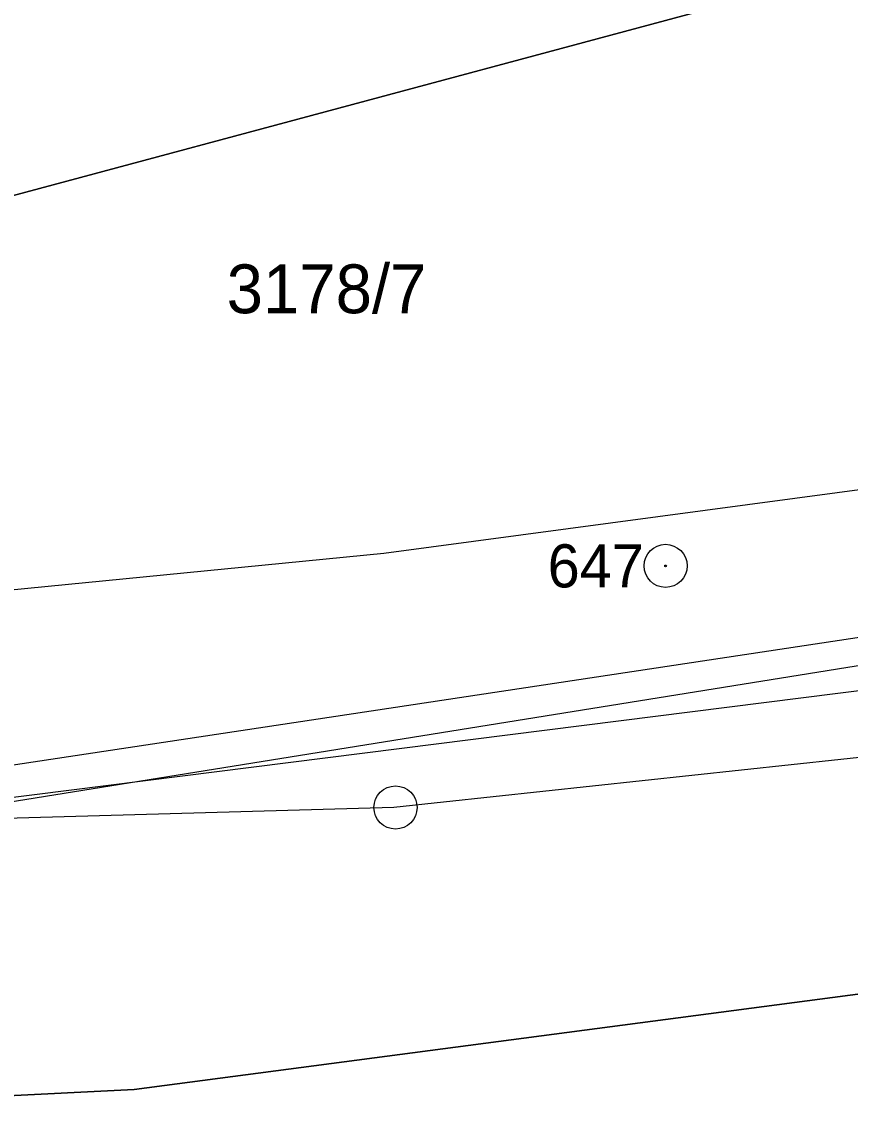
# Model space of a CAD drawing. Extents: x -728802 to -728097, y -1073200 to -1072700.
# Drawn here: x -728474.88 to -728446.06, y -1073055.04 to -1073016.93 of the extents above; entities that cross this region are included whole.
import ezdxf

# ---------------------------------------------------------------- set-up
doc = ezdxf.new("R2010")
doc.units = 0
for name, color, linetype in [('A5_JŽM', 7, 'Continuous'), ('body_ZBP', 7, 'Continuous'), ('Hranice parcel', 7, 'Continuous')]:
    doc.layers.add(name, color=color, linetype=linetype)

msp = doc.modelspace()

# ---------------------------------------------------------------- linework, layer by layer
at = {"layer": 'A5_JŽM'}
for points in [[(-728320.8, -1073026.914), (-728374.008, -1073033.722), (-728429.095, -1073040.747), (-728461.932, -1073044.273), (-728481.199, -1073044.815), (-728499.353, -1073043.648), (-728506.01, -1073042.737), (-728514.574, -1073041.329), (-728535.848, -1073035.998), (-728561.353, -1073026.113), (-728583.963, -1073013.524), (-728603.757, -1072998.891), (-728619.185, -1072984.418), (-728634.193, -1072966.825), (-728646.078, -1072949.194), (-728656.182, -1072930.072), (-728664.987, -1072910.227), (-728668.627, -1072901.808), (-728681.252, -1072876.016), (-728691.886, -1072859.663)], [(-728498.81, -1073037.92), (-728499.78, -1073032.61), (-728497.54, -1073030.15), (-728493.68, -1073027.94), (-728443.97, -1073014.59), (-728443.68, -1073014.51), (-728441.09, -1073023.23), (-728428.92, -1073019.94), (-728429.82, -1073016.43), (-728427.49, -1073015.84), (-728421.24, -1073014.23), (-728422.34, -1073010.27), (-728422.77, -1073008.34), (-728418.21, -1073007), (-728380.57, -1072997.2), (-728343.1, -1072987.57), (-728330.49, -1072984.52), (-728326.79, -1072988.95)], [(-728327.13, -1073038.08), (-728361.73, -1073039.5), (-728434.43, -1073049.27), (-728470.97, -1073054.08), (-728490.19, -1073055.04), (-728500.77, -1073053.31), (-728499.61, -1073049.44), (-728498.79, -1073046.71), (-728497.84, -1073043.2), (-728498.81, -1073037.92)]]:
    msp.add_lwpolyline(points, dxfattribs=at)
msp.add_circle((-728461.879, -1073044.267), 0.75, dxfattribs=at)
at = {"layer": 'body_ZBP'}
for p, q in [((-728517.378, -1073049.136), (-728351.413, -1073024.133)), ((-728498.137, -1073047.735), (-728351.407, -1073024.171)), ((-728517.364, -1073049.238), (-728403.486, -1073034.863))]:
    msp.add_line(p, q, dxfattribs=at)
at = {"layer": 'Hranice parcel'}
for points in [[(-728443.97, -1073014.59), (-728493.68, -1073027.94), (-728497.54, -1073030.15), (-728499.78, -1073032.61)], [(-728428.94, -1073031.04), (-728435.33, -1073031.82), (-728462.29, -1073035.43), (-728488.6, -1073038.02), (-728488.39, -1073034.38), (-728493.51, -1073034.35), (-728493.84, -1073039.37)], [(-728499.61, -1073049.44), (-728500.77, -1073053.31), (-728490.19, -1073055.04), (-728470.97, -1073054.08), (-728434.43, -1073049.27), (-728361.73, -1073039.5), (-728327.13, -1073038.08)]]:
    msp.add_lwpolyline(points, dxfattribs=at)
for radius in [0.75, 0.03]:
    msp.add_circle((-728452.48, -1073035.86), radius, dxfattribs=at)

# ---------------------------------------------------------------- texts
for s, height, p in [('3178/7', 1.7, (-728467.755, -1073027.07)), ('647', 1.5, (-728456.583, -1073036.61))]:
    msp.add_text(s, height=height, dxfattribs=at).set_placement(p)

doc.saveas('drawing.dxf')
